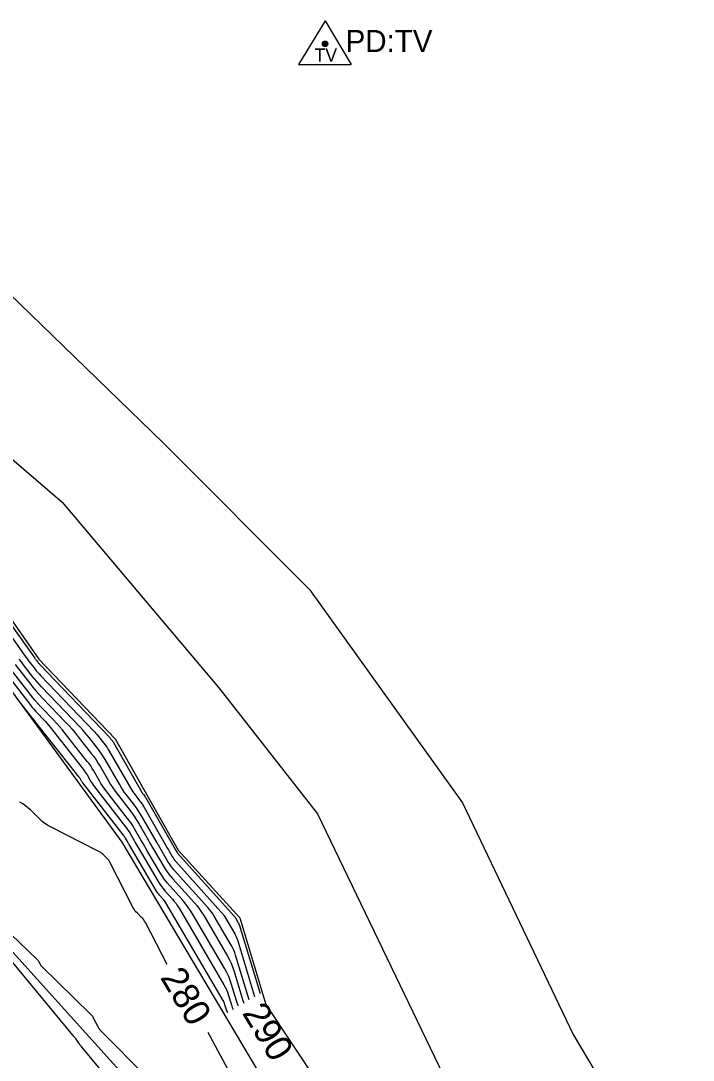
# Model space of a CAD drawing. Extents: x 1574966 to 1597594, y 720505 to 737840.
# Drawn here: x 1578012.4 to 1578164.8, y 724228.5 to 724464.1 of the extents above; entities that cross this region are included whole.
import ezdxf

# ---------------------------------------------------------------- set-up
doc = ezdxf.new("R2010")
doc.units = 0
for name, color, linetype in [('Default', 7, 'Continuous'), ('R_Contour Annot', 7, 'Continuous'), ('R_Contours', 7, 'Continuous'), ('S_BREAKLINE', 7, 'Continuous'), ('S_SECONDARY_CTL', 7, 'Continuous'), ('S_SECONDARY_CTL_ANNOT', 7, 'Continuous'), ('S_STREAM', 7, 'Continuous')]:
    doc.layers.add(name, color=color, linetype=linetype)

msp = doc.modelspace()

# ---------------------------------------------------------------- linework, layer by layer
at = {"layer": 'Default'}
msp.add_lwpolyline([(1578081.36, 724458.84), (1578081.36, 724458.89), (1578081.36, 724458.84), (1578081.31, 724458.84), (1578081.36, 724458.84), (1578081.36, 724458.79), (1578081.36, 724458.84), (1578081.41, 724458.84)], dxfattribs=at)
msp.add_lwpolyline([(1578081.36, 724458.84), (1578081.36, 724458.89), (1578081.36, 724458.84), (1578081.31, 724458.84), (1578081.36, 724458.84), (1578081.36, 724458.79), (1578081.36, 724458.84), (1578081.41, 724458.84)], dxfattribs=at)
msp.add_lwpolyline([(1578081.36, 724458.84), (1578081.36, 724458.89), (1578081.36, 724458.84), (1578081.31, 724458.84), (1578081.36, 724458.84), (1578081.36, 724458.79), (1578081.36, 724458.84), (1578081.41, 724458.84)], dxfattribs=at)
at = {"layer": 'R_Contours'}
for points in [[(1578008.53, 724329.53), (1578015.54, 724319.62), (1578015.62, 724319.51), (1578015.7, 724319.4), (1578015.78, 724319.28), (1578015.87, 724319.17), (1578016.21, 724318.73), (1578016.3, 724318.62), (1578016.39, 724318.51), (1578016.49, 724318.41), (1578016.58, 724318.3), (1578032.37, 724301.81), (1578032.46, 724301.71), (1578032.55, 724301.61), (1578032.64, 724301.51), (1578032.72, 724301.4), (1578033.06, 724300.98), (1578033.14, 724300.87), (1578033.21, 724300.76), (1578033.29, 724300.65), (1578033.36, 724300.54), (1578039.92, 724289.11), (1578039.98, 724289.01), (1578040.04, 724288.91), (1578040.1, 724288.82), (1578040.17, 724288.73), (1578040.46, 724288.36), (1578040.52, 724288.27), (1578040.59, 724288.18), (1578040.65, 724288.08), (1578040.71, 724287.98), (1578047.36, 724276.37), (1578047.4, 724276.3), (1578047.45, 724276.22), (1578047.49, 724276.15), (1578047.53, 724276.07), (1578047.71, 724275.77), (1578047.76, 724275.7), (1578047.8, 724275.63), (1578047.86, 724275.56), (1578047.91, 724275.49), (1578060.76, 724261.19), (1578060.83, 724261.11), (1578060.9, 724261.02), (1578060.96, 724260.93), (1578061.02, 724260.84), (1578061.69, 724259.69), (1578061.74, 724259.6), (1578061.79, 724259.5), (1578061.83, 724259.39), (1578061.87, 724259.29), (1578066.61, 724243.7)], [(1578008.35, 724327.18), (1578013.3, 724320.17), (1578013.58, 724319.79), (1578013.86, 724319.41), (1578014.14, 724319.03), (1578014.43, 724318.65), (1578015.59, 724317.16), (1578015.88, 724316.79), (1578016.19, 724316.43), (1578016.5, 724316.07), (1578016.82, 724315.73), (1578029.08, 724302.92), (1578029.39, 724302.59), (1578029.7, 724302.25), (1578029.99, 724301.9), (1578030.28, 724301.54), (1578031.41, 724300.11), (1578031.69, 724299.74), (1578031.95, 724299.37), (1578032.2, 724298.98), (1578032.43, 724298.59), (1578037.32, 724290.08), (1578037.53, 724289.72), (1578037.76, 724289.37), (1578038, 724289.02), (1578038.26, 724288.68), (1578039.29, 724287.35), (1578039.55, 724287.01), (1578039.79, 724286.67), (1578040.02, 724286.31), (1578040.23, 724285.95), (1578045.31, 724277.08), (1578045.49, 724276.78), (1578045.66, 724276.48), (1578045.84, 724276.18), (1578046.01, 724275.88), (1578046.72, 724274.68), (1578046.9, 724274.38), (1578047.1, 724274.1), (1578047.31, 724273.83), (1578047.54, 724273.56), (1578057.75, 724262.18), (1578057.99, 724261.9), (1578058.22, 724261.61), (1578058.43, 724261.31), (1578058.62, 724261), (1578060.87, 724257.16), (1578061.05, 724256.84), (1578061.21, 724256.5), (1578061.35, 724256.16), (1578061.47, 724255.81), (1578065.38, 724242.96)], [(1578064.15, 724242.22), (1578061.07, 724252.32), (1578060.87, 724252.92), (1578060.64, 724253.51), (1578060.37, 724254.08), (1578060.06, 724254.63), (1578056.22, 724261.16), (1578055.89, 724261.69), (1578055.54, 724262.21), (1578055.16, 724262.7), (1578054.75, 724263.18), (1578047.16, 724271.63), (1578046.77, 724272.09), (1578046.4, 724272.57), (1578046.05, 724273.07), (1578045.73, 724273.59), (1578044.49, 724275.68), (1578044.18, 724276.21), (1578043.88, 724276.74), (1578043.57, 724277.26), (1578043.27, 724277.79), (1578039.76, 724283.92), (1578039.38, 724284.55), (1578038.99, 724285.16), (1578038.57, 724285.76), (1578038.13, 724286.34), (1578036.34, 724288.64), (1578035.9, 724289.23), (1578035.49, 724289.82), (1578035.09, 724290.44), (1578034.72, 724291.06), (1578031.51, 724296.65), (1578031.11, 724297.32), (1578030.69, 724297.97), (1578030.24, 724298.61), (1578029.77, 724299.23), (1578027.83, 724301.69), (1578027.34, 724302.29), (1578026.84, 724302.89), (1578026.32, 724303.47), (1578025.79, 724304.04), (1578017.06, 724313.15), (1578016.52, 724313.74), (1578015.98, 724314.35), (1578015.46, 724314.96), (1578014.96, 724315.59), (1578012.99, 724318.14), (1578012.5, 724318.78), (1578012.02, 724319.42)], [(1578006.73, 724319.08), (1578014.62, 724308.9), (1578014.96, 724308.47), (1578015.32, 724308.05), (1578015.68, 724307.64), (1578016.06, 724307.24), (1578017.57, 724305.66), (1578017.95, 724305.26), (1578018.31, 724304.85), (1578018.67, 724304.43), (1578019.01, 724304), (1578026.52, 724294.47), (1578026.75, 724294.15), (1578026.98, 724293.83), (1578027.19, 724293.51), (1578027.39, 724293.17), (1578028.17, 724291.81), (1578028.38, 724291.47), (1578028.59, 724291.15), (1578028.81, 724290.82), (1578029.05, 724290.51), (1578036.12, 724281.42), (1578036.4, 724281.05), (1578036.66, 724280.68), (1578036.91, 724280.29), (1578037.14, 724279.9), (1578038.06, 724278.3), (1578038.28, 724277.9), (1578038.51, 724277.5), (1578038.75, 724277.11), (1578038.98, 724276.71), (1578043.52, 724269.01), (1578043.86, 724268.47), (1578044.23, 724267.94), (1578044.62, 724267.43), (1578045.03, 724266.95), (1578046.75, 724265.03), (1578047.17, 724264.54), (1578047.56, 724264.03), (1578047.93, 724263.51), (1578048.27, 724262.96), (1578058.44, 724245.65), (1578058.73, 724245.11), (1578058.99, 724244.57), (1578059.22, 724244), (1578059.42, 724243.43), (1578060.13, 724241.09), (1578060.32, 724240.52), (1578060.52, 724240.03)], [(1578061.74, 724240.77), (1578061.61, 724241.09), (1578061.3, 724242.01), (1578060.17, 724245.72), (1578059.86, 724246.64), (1578059.5, 724247.53), (1578059.09, 724248.4), (1578058.63, 724249.25), (1578051.29, 724261.73), (1578050.76, 724262.58), (1578050.19, 724263.4), (1578049.58, 724264.2), (1578048.93, 724264.96), (1578046.24, 724267.95), (1578045.59, 724268.71), (1578044.98, 724269.51), (1578044.41, 724270.33), (1578043.88, 724271.18), (1578041.02, 724276.02), (1578040.66, 724276.63), (1578040.3, 724277.25), (1578039.95, 724277.86), (1578039.59, 724278.48), (1578038.17, 724280.95), (1578037.81, 724281.57), (1578037.43, 724282.16), (1578037.02, 724282.75), (1578036.59, 724283.32), (1578031.66, 724289.65), (1578031.27, 724290.17), (1578030.9, 724290.71), (1578030.54, 724291.26), (1578030.21, 724291.82), (1578028.9, 724294.1), (1578028.56, 724294.66), (1578028.21, 724295.21), (1578027.83, 724295.74), (1578027.44, 724296.26), (1578022.44, 724302.6), (1578021.8, 724303.4), (1578021.14, 724304.18), (1578020.46, 724304.94), (1578019.76, 724305.69), (1578016.93, 724308.65), (1578016.23, 724309.4), (1578015.55, 724310.16), (1578014.9, 724310.95), (1578014.26, 724311.75), (1578008.92, 724318.64)], [(1578011.1, 724318.2), (1578014.34, 724314.02), (1578015.05, 724313.13), (1578015.78, 724312.26), (1578016.53, 724311.41), (1578017.31, 724310.58), (1578022.49, 724305.16), (1578023.25, 724304.35), (1578023.98, 724303.53), (1578024.7, 724302.69), (1578025.39, 724301.83), (1578028.35, 724298.06), (1578028.91, 724297.33), (1578029.44, 724296.58), (1578029.93, 724295.81), (1578030.41, 724295.02), (1578032.24, 724291.83), (1578032.71, 724291.05), (1578033.21, 724290.28), (1578033.73, 724289.52), (1578034.28, 724288.79), (1578037.06, 724285.21), (1578037.64, 724284.44), (1578038.19, 724283.65), (1578038.71, 724282.84), (1578039.21, 724282.01), (1578041.22, 724278.5), (1578041.65, 724277.75), (1578042.09, 724276.99), (1578042.53, 724276.24), (1578042.97, 724275.49), (1578044.74, 724272.49), (1578045.2, 724271.75), (1578045.69, 724271.04), (1578046.22, 724270.36), (1578046.79, 724269.7), (1578051.75, 724264.17), (1578052.32, 724263.5), (1578052.86, 724262.8), (1578053.36, 724262.08), (1578053.83, 724261.32), (1578059.25, 724252.1), (1578059.68, 724251.32), (1578060.06, 724250.52), (1578060.39, 724249.69), (1578060.68, 724248.84), (1578062.73, 724242.1), (1578062.94, 724241.49)], [(1578059.32, 724239.31), (1578059.23, 724239.48), (1578059.12, 724239.7), (1578059.03, 724239.94), (1578058.95, 724240.17), (1578058.66, 724241.13), (1578058.58, 724241.37), (1578058.49, 724241.6), (1578058.38, 724241.83), (1578058.26, 724242.05), (1578045.24, 724264.19), (1578045.09, 724264.43), (1578044.93, 724264.66), (1578044.76, 724264.89), (1578044.58, 724265.1), (1578043.83, 724265.94), (1578043.64, 724266.15), (1578043.47, 724266.38), (1578043.31, 724266.61), (1578043.16, 724266.85), (1578036.94, 724277.4), (1578036.83, 724277.58), (1578036.73, 724277.76), (1578036.62, 724277.94), (1578036.52, 724278.12), (1578036.11, 724278.84), (1578036, 724279.01), (1578035.89, 724279.19), (1578035.77, 724279.36), (1578035.65, 724279.52), (1578026.43, 724291.37), (1578026.35, 724291.47), (1578026.28, 724291.58), (1578026.21, 724291.69), (1578026.14, 724291.8), (1578025.89, 724292.24), (1578025.82, 724292.35), (1578025.75, 724292.46), (1578025.68, 724292.57), (1578025.6, 724292.67), (1578015.58, 724305.4), (1578015.53, 724305.45), (1578015.48, 724305.51), (1578015.44, 724305.57), (1578015.39, 724305.62), (1578015.18, 724305.83), (1578015.13, 724305.89), (1578015.08, 724305.94), (1578015.03, 724306), (1578014.99, 724306.06), (1578011.49, 724310.57)], [(1578045.57, 724250.27), (1578040.63, 724259.73), (1578040.45, 724260.05), (1578040.24, 724260.34), (1578040.01, 724260.62), (1578039.76, 724260.89), (1578038.72, 724261.91), (1578038.47, 724262.17), (1578038.24, 724262.45), (1578038.04, 724262.75), (1578037.86, 724263.07), (1578032.66, 724273.3), (1578032.5, 724273.58), (1578032.33, 724273.85), (1578032.13, 724274.09), (1578031.9, 724274.32), (1578030.97, 724275.21), (1578030.73, 724275.42), (1578030.48, 724275.62), (1578030.21, 724275.79), (1578029.93, 724275.95), (1578019.09, 724281.43), (1578018.44, 724281.8), (1578017.82, 724282.2), (1578017.24, 724282.66), (1578016.68, 724283.16), (1578014.54, 724285.25), (1578013.99, 724285.75), (1578013.41, 724286.22), (1578012.8, 724286.65), (1578012.17, 724287.05)], [(1578044.97, 724208.85), (1578026.04, 724231.73), (1578025.91, 724231.9), (1578025.78, 724232.06), (1578025.66, 724232.23), (1578025.54, 724232.41), (1578024.94, 724233.29), (1578024.88, 724233.37), (1578024.82, 724233.46), (1578024.75, 724233.54), (1578024.69, 724233.62), (1578024.41, 724233.94), (1578024.34, 724234.02), (1578024.27, 724234.1), (1578024.2, 724234.18), (1578024.13, 724234.26), (1578001.83, 724261.11)], [(1578004.24, 724262.67), (1578016.07, 724251.38), (1578016.18, 724251.26), (1578016.28, 724251.14), (1578016.37, 724251), (1578016.45, 724250.86), (1578016.74, 724250.29), (1578016.82, 724250.14), (1578016.91, 724250.01), (1578017.01, 724249.89), (1578017.12, 724249.77), (1578028.19, 724238.99), (1578028.34, 724238.84), (1578028.47, 724238.67), (1578028.6, 724238.49), (1578028.7, 724238.3), (1578029.88, 724236.05), (1578029.98, 724235.87), (1578030.1, 724235.7), (1578030.22, 724235.54), (1578030.36, 724235.39), (1578041.05, 724224.62)], [(1578059.34, 724226.51), (1578054.87, 724234.86)]]:
    msp.add_lwpolyline(points, dxfattribs=at)
at = {"layer": 'S_BREAKLINE'}
for p, q in [((1578004.46, 724407.33), (1578044.64, 724368.4)), ((1578075.05, 724181.63), (1577881.29, 724395.93)), ((1577987.39, 724384.46), (1578021.71, 724355.01)), ((1578044.64, 724368.4), (1578077.81, 724335.18)), ((1578021.71, 724355.01), (1578057.29, 724312.92)), ((1578077.81, 724335.18), (1578112.5, 724286.88)), ((1578057.29, 724312.92), (1578079.63, 724284.39)), ((1578112.5, 724286.88), (1578137.65, 724234.36)), ((1578079.63, 724284.39), (1578110.5, 724220.3)), ((1578137.65, 724234.36), (1578164.85, 724188.72))]:
    msp.add_line(p, q, dxfattribs=at)
at = {"layer": 'S_SECONDARY_CTL'}
for p, q in [((1578081.37, 724464.06), (1578075.35, 724454.15)), ((1578081.37, 724464.06), (1578075.35, 724454.15)), ((1578081.37, 724464.06), (1578075.35, 724454.15)), ((1578081.37, 724464.04), (1578075.35, 724454.13)), ((1578081.37, 724464.04), (1578075.35, 724454.13)), ((1578081.37, 724464.04), (1578075.35, 724454.13)), ((1578081.37, 724464.06), (1578087.27, 724454.15)), ((1578081.37, 724464.06), (1578087.27, 724454.15)), ((1578081.37, 724464.06), (1578087.27, 724454.15)), ((1578081.37, 724464.04), (1578087.27, 724454.13)), ((1578081.37, 724464.04), (1578087.27, 724454.13)), ((1578081.37, 724464.04), (1578087.27, 724454.13)), ((1578075.35, 724454.15), (1578087.27, 724454.15)), ((1578075.35, 724454.15), (1578087.27, 724454.15)), ((1578075.35, 724454.15), (1578087.27, 724454.15)), ((1578075.35, 724454.13), (1578087.27, 724454.13)), ((1578075.35, 724454.13), (1578087.27, 724454.13)), ((1578075.35, 724454.13), (1578087.27, 724454.13))]:
    msp.add_line(p, q, dxfattribs=at)
for centre, radius in [((1578081.37, 724458.83), 0.622), ((1578081.37, 724458.83), 0.622), ((1578081.37, 724458.83), 0.622), ((1578081.37, 724458.82), 0.622), ((1578081.37, 724458.82), 0.622), ((1578081.37, 724458.82), 0.622), ((1578081.37, 724458.83), 0.365), ((1578081.37, 724458.83), 0.365), ((1578081.37, 724458.83), 0.365), ((1578081.37, 724458.82), 0.365), ((1578081.37, 724458.82), 0.365), ((1578081.37, 724458.82), 0.365), ((1578081.37, 724458.83), 0.207), ((1578081.37, 724458.83), 0.207), ((1578081.37, 724458.83), 0.207), ((1578081.37, 724458.82), 0.207), ((1578081.37, 724458.82), 0.207), ((1578081.37, 724458.82), 0.207)]:
    msp.add_circle(centre, radius, dxfattribs=at)
at = {"layer": 'S_STREAM'}
for p, q in [((1578000.75, 724341.78), (1578016.48, 724319.39)), ((1577994.83, 724333.26), (1578035.26, 724277.97)), ((1578016.48, 724319.39), (1578033.74, 724301.34)), ((1578033.74, 724301.34), (1578048.04, 724276.14)), ((1578035.26, 724277.97), (1578065.75, 724226.72)), ((1578048.04, 724276.14), (1578062.03, 724260.77)), ((1578062.03, 724260.77), (1578067.92, 724241.17)), ((1578067.92, 724241.17), (1578086.2, 724213.69))]:
    msp.add_line(p, q, dxfattribs=at)

# ---------------------------------------------------------------- texts
at = {"layer": 'R_Contour Annot'}
for s, rotation, p in [('280', 301.1296, (1578043.85, 724247.3)), ('290', 301.0549, (1578062.43, 724239.25))]:
    msp.add_text(s, height=6, rotation=rotation, dxfattribs=at).set_placement(p)
at = {"layer": 'S_SECONDARY_CTL'}
for p in [(1578078.96, 724454.81), (1578078.96, 724454.81), (1578078.96, 724454.81), (1578078.96, 724454.8), (1578078.96, 724454.8), (1578078.96, 724454.8)]:
    msp.add_text('TV', height=3, rotation=360, dxfattribs=at).set_placement(p)
at = {"layer": 'S_SECONDARY_CTL_ANNOT'}
msp.add_text('PD:TV', height=5, dxfattribs=at).set_placement((1578086.03, 724456.97))

doc.saveas('drawing.dxf')
